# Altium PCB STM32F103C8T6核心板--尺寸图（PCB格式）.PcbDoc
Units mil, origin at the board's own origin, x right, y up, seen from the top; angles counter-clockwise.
Board outline 901.92 x 2104.63 mil, 2 copper layers (Top Layer, Bottom Layer); 5 components, 0 nets, 65 pads, 0 vias.
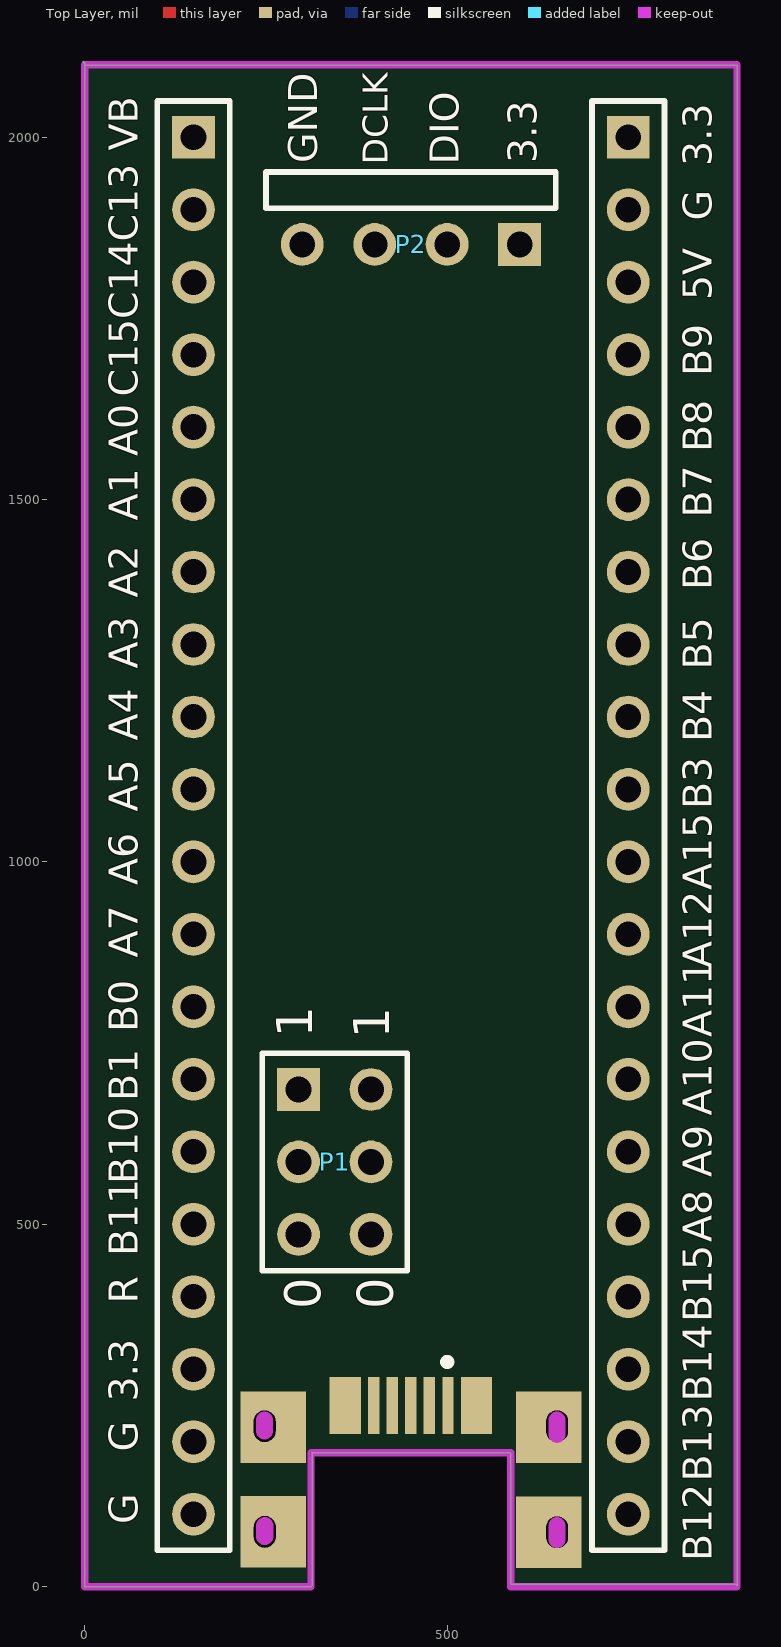
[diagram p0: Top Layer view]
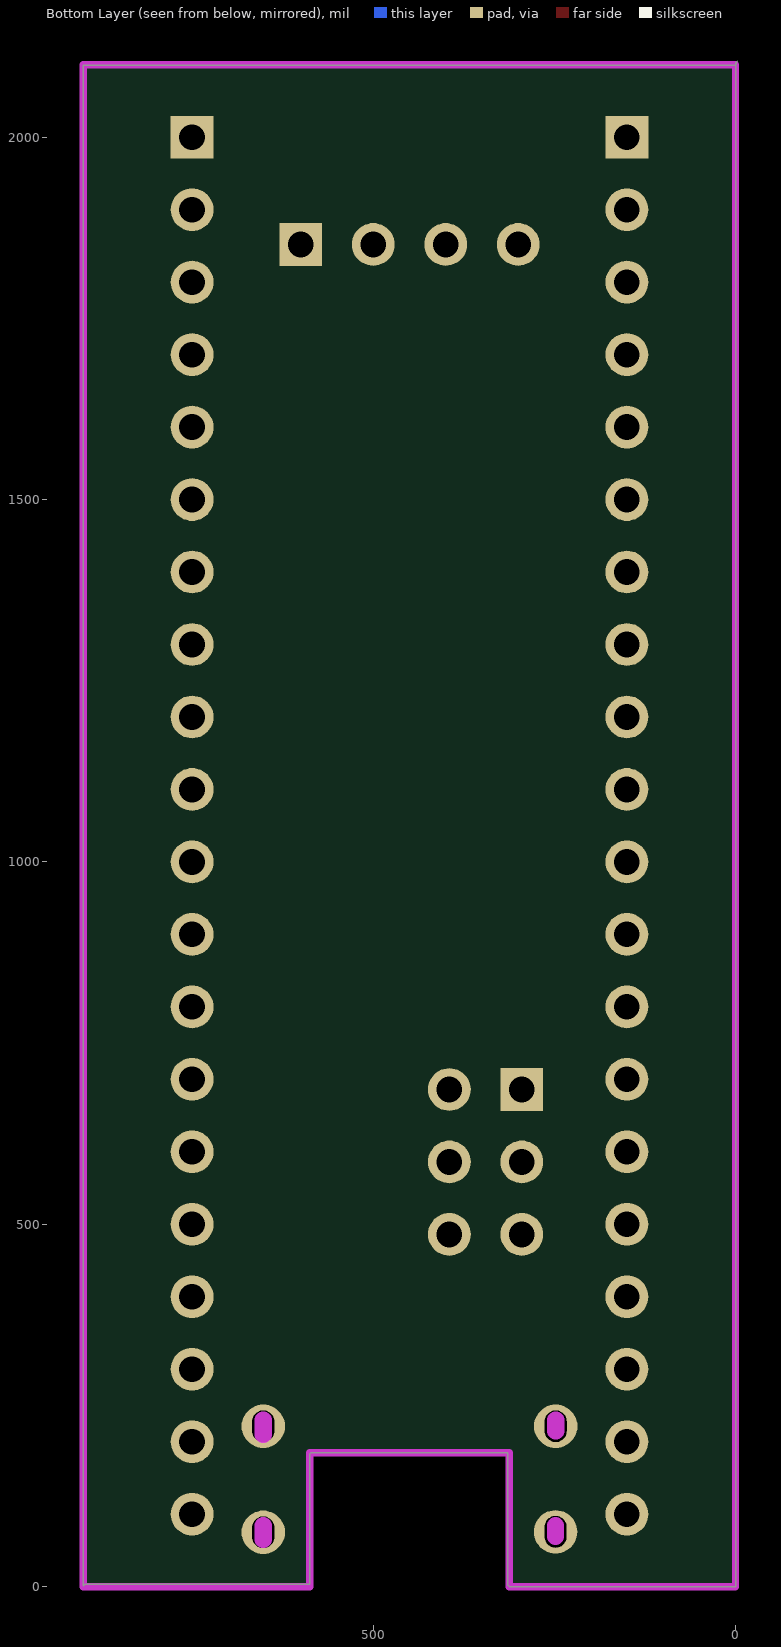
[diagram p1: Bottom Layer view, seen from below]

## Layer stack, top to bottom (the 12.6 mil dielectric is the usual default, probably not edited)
Top Solder: solder mask 0.4, Solder Resist, Dk 3.5
Top Layer: signal copper 1.4
Dielectric1: dielectric 12.6, FR-4, Dk 4.8
Bottom Layer: signal copper 1.4
Bottom Solder: solder mask 0.4, Solder Resist, Dk 3.5

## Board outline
0,2100 1,2099 900,2099 900,1 898,3 587.8,3 587.8,182.91 585.83,184.88 314.17,184.88 314.17,1.97 312.2,0 0,0 0,2102.71 -1.92,2104.63

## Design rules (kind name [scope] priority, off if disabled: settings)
Clearance [All] p1: gap=8
FabricationTestPointUsage TestPointUsage [All] p1: valid=0 allowmultiple=FALSE
FabricationTestpoint Testpoint [(IsPad And (OnTopLayer Or OnBottomLayer))] p1: side=3 testpointundercomponent=TRUE minsize=40 maxsize=100 preferedsize=60 minholesize=0 maxholesize=40 preferedholesize=32 testpointgrid=1 allowsidetop=TRUE allowsidebottom=TRUE usegrid=TRUE gridtolerance=0.01
HoleToHoleClearance [All] p1: gap=0 allowstackedmicrovias=TRUE
MinimumSolderMaskSliver [All] p1: minsoldermaskwidth=0
PolygonConnect PolygonConnect_1 [All vs (InPadClass('All Pads'))] p1: connectstyle=Relief reliefconductorwidth=20 reliefentries=4 polygonreliefangle="90 Angle" airgapwidth=10
PolygonConnect [All] p2: connectstyle=Direct reliefconductorwidth=20 reliefentries=4 polygonreliefangle="90 Angle" airgapwidth=10
RoutingVias [All] p1: holewidth=15 width=30 viastyle="Through Hole" minholewidth=10 minwidth=20 maxholewidth=50 maxwidth=100
SilkToSilkClearance [All] p1: silktosilkclearance=0
SilkToSolderMaskClearance SilkscreenOverComponentPads [IsPad] p1: minsilkscreentomaskgap=0 clearancetoexposedcopper=TRUE
SolderMaskExpansion [All] p1: expansion=4
Width [All] p1: maxlimit=50 minlimit=10 preferedwidth=10 minimp=50.000000 maximp=50.000000 favimp=50.000000
23 further rules are at their usual default settings.

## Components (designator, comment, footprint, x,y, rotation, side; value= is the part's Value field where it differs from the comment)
P1 "Header 3X2" HDR2X3 295,686 r270 top
P2 "SWD" HDR1X4H 600,1852 r180 top
P3 "Header 20" HDR1X20 150,2000 r270 top locked
P4 "Header 20" HDR1X20 750,2000 r270 top locked
? "Comment" "MICRO_USB_V2 - DUPLICATE" 450,240 r0 top locked

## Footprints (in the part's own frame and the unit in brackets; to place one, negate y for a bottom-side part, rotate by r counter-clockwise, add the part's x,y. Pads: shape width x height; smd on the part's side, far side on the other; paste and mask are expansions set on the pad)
HDR1X4H [mm] "Connector; Header; 4 Position; Right Angle"
  rect 1.5x1.5 hole 0.9: 1(0,0)
  round 1.5 hole 0.9: 2(2.54,0) 3(5.08,0) 4(7.62,0)
  silkscreen extent -1.27,-2.54 8.89,-1.27
HDR1X20 [mm] "Connector; Header; 20 Position"
  rect 1.5x1.5 hole 0.9: 1(0,0)
  round 1.5 hole 0.9: 2(2.54,0) 3(5.08,0) 4(7.62,0) 5(10.16,0) 6(12.7,0) 7(15.24,0) 8(17.78,0) 9(20.32,0) 10(22.86,0) 11(25.4,0) 12(27.94,0) 13(30.48,0) 14(33.02,0) 15(35.56,0) 16(38.1,0) 17(40.64,0) 18(43.18,0) 19(45.72,0) 20(48.26,0)
  silkscreen extent -1.27,-1.27 49.53,1.27
HDR2X3 [mm] "Connector; Header; 3x2 Position"
  rect 1.5x1.5 hole 0.9: 1(0,0)
  round 1.5 hole 0.9: 2(0,2.54) 3(2.54,0) 4(2.54,2.54) 5(5.08,0) 6(5.08,2.54)
  silkscreen extent -1.27,-1.27 6.35,3.81
"MICRO_USB_V2 - DUPLICATE" [mm]
  round 1.524 hole 0.762 slot 1.1 at 90 deg: 0(-5.125,-0.475) 0(-5.12,-4.175) 0(5.125,-4.191) 0(5.125,-0.475)
  rect 0.4x2 smd: 1(1.3,0.254) 2(0.65,0.254) 3(0,0.254) 4(-0.65,0.254) 5(-1.3,0.254)
  rect 2.3x2.5 smd: ""(-4.826,-4.175) ""(-4.826,-0.508) ""(4.826,-4.191) ""(4.826,-0.508)
  rect 1.1x2 smd: ""(-2.3,0.254) ""(2.3,0.254)
  Keep-Out Layer lines w0.254: -3.5,-6.096 -3.5,-1.4 ; -3.45,-1.4 3.45,-1.4 ; 3.5,-6.096 3.5,-1.4
  Keep-Out Layer lines w0.6: -5.125,-0.635 -5.125,-0.262 ; -5.12,-4.335 -5.12,-3.962 ; 5.125,-4.445 5.125,-3.962 ; 5.125,-0.762 5.125,-0.262
  silkscreen extent 1.15,1.65 1.4,1.9

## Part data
P1: "Header, 3-Pin, Dual row"
P2: library part "Header 4", "Header, 4-Pin"
P3 P4: "Header, 20-Pin"

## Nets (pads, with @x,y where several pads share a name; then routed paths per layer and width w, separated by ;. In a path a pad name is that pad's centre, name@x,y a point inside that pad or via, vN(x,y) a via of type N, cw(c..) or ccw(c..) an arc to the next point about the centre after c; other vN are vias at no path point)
pads on no net: ?. ?.0 ?.1 ?.2 ?.3 ?.4 ?.5 P1.1 P1.2 P1.3 P1.4 P1.5 P1.6 P2.1 P2.2 P2.3 P2.4 P3.1 P3.2 P3.3 P3.4 P3.5 P3.6 P3.7 P3.8 P3.9 P3.10 P3.11 P3.12 P3.13 P3.14 P3.15 P3.16 P3.17 P3.18 P3.19 P3.20 P4.1 P4.2 P4.3 P4.4 P4.5 P4.6 P4.7 P4.8 P4.9 P4.10 P4.11 P4.12 P4.13 P4.14 P4.15 P4.16 P4.17 P4.18 P4.19 P4.20

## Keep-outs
Keep-Out Layer:
  lines w10: 312.2,0 0,0 0,2100 900,2100 900,0 850,0 587.8,0 ; 900,1 900,2099

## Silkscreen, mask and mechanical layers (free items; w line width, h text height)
Top Overlay:
  text "VB" at 73,1981 h40 r90
  text "GND" at 321,1964 h40 r90
  text "3.3" at 624,1964 h40 r90
  text "DCLK" at 418,1962 h35 r90
  text "DIO" at 516,1962 h40 r90
  text "3.3" at 865,1960 h40 r90
  text "G" at 865,1885 h40 r90
  text "5V" at 865,1775 h40 r90
  text "B9" at 865,1670 h40 r90
  text "C15C14C13" at 73,1642 h40 r90
  text "B8" at 865,1565 h40 r90
  text "A0" at 73,1560 h40 r90
  text "B7" at 865,1475 h40 r90
  text "A1" at 73,1471 h40 r90
  text "B6" at 865,1375 h40 r90
  text "A2" at 73,1364.29 h40 r90
  text "A3" at 73,1266.43 h40 r90
  text "B5" at 865,1265 h40 r90
  text "A4" at 73,1167 h40 r90
  text "B4" at 865,1165 h40 r90
  text "B3" at 865,1073 h40 r90
  text "A5" at 73,1069 h40 r90
  text "A6" at 73,968 h40 r90
  text "A15" at 865,961 h40 r90
  text "A7" at 73,868 h40 r90
  text "A12" at 865,853 h40 r90
  text "B0" at 73,765 h40 r90
  text "A11" at 865,758 h40 r90
  text "B1" at 73,670 h40 r90
  text "A10" at 865,650 h40 r90
  text "A9" at 865,565 h40 r90
  text "B10" at 73,555 h40 r90
  text "A8" at 865,475 h40 r90
  text "B11" at 73,456 h40 r90
  text "R" at 73,390 h40 r90
  text "B15" at 865,365 h40 r90
  text "3.3" at 73,255 h40 r90
  text "B14" at 865,255 h40 r90
  text "G" at 73,186 h40 r90
  text "B13" at 865,145 h40 r90
  text "G" at 73,86 h40 r90
  text "B12" at 865,35 h40 r90

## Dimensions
0,2100 to 900,2100 on Top Overlay
0,2100 to 900,2100 on Top Overlay
900,2100 to 900,0 on Top Overlay
982,2100 to 972,0 on Top Overlay
150,2000 to 150,100 on Top Overlay
62,2000 to 62,100 on Top Overlay
150,100 to 750,100 on Top Overlay
150,56.47 to 750,31 on Top Overlay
